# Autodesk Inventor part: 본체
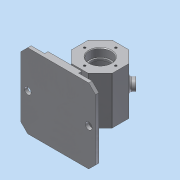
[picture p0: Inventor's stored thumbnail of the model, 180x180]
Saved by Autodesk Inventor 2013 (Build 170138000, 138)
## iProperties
Created: 2018-06
Part Number: 본체
Material: 알루미늄 6061
Document SubType Name: Modeling
Designer: Administrator
Density: 2.71 g/cm^3
Mass: 554.044 g
Surface Area: 601.935 cm^2
Volume: 204.444 cm^3
Author: Administrator
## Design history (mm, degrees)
sketch "스케치1" dims "d0" = 60
  geometry: L1 (12.426, 30)-(30, 12.426); L2 (30, 12.426)-(30, -12.426); L3 (30, -12.426)-(12.426, -30); L4 (12.426, -30)-(-12.426, -30); L5 (-12.426, -30)-(-30, -12.426); L6 (-30, -12.426)-(-30, 12.426); L7 (-30, 12.426)-(-12.426, 30); L8 (-12.426, 30)-(12.426, 30); L9 (55, -62)-(-55, -62); L10 (-55, -62)-(-55, -57); L11 (-55, -57)-(55, -57); L12 (55, -57)-(55, -62); 6 further points
  constraints: 24 end point, 3 coincident, 3 vertical alignment, 2 midpoint, 2 parallel, 1 horizontal, 1 perpendicular, 19 other
  dimensions: "d1" = 5 distance of L9.end L10.end; "d2" = 62 distance from line of point (0, 0) L9; "d3" = 110 distance of L9.start L9.end
extrude "돌출1" new body sketch "스케치1" stored distance "d4" = 70; taper "d5" = 0 deg
extrude "돌출2" join sketch "스케치1" stored distance "d6" = 110; taper "d7" = 0 deg
sketch "스케치2"
  geometry: L1 (0, 0)-(0, 110) reference; L2 (110, 0)-(0, 0) reference; L3 (110, 0)-(110, 110) reference; L4 (0, 110)-(110, 110) reference; L5 (30, 110)-(80, 110); L6 (80, 110)-(80, 0); L7 (80, 0)-(30, 0); L8 (30, 0)-(30, 110); 1 further point
  constraints: 8 end point, 2 parallel, 1 collinear, 1 horizontal, 1 perpendicular, 1 point on line
  dimensions: "d9" = 30 distance between parallel lines of L1 L8; "d10" = 30 distance between parallel lines of L3 L6
extrude "돌출3" join sketch "스케치2" distance "d11" = 5; taper "d12" = 0 deg
hole "구멍1" diameter "d15" = 28; stored, may be unused: countersink angle "d19" = 90 deg, drill point angle "d21" = 0 deg; dims "d13" = 30, "d14" = 30, "d16" = 6, "d17" = 4, "d18" = 2, "d20" = 12
hole "구멍2" diameter "d24" = 32; stored, may be unused: countersink angle "d28" = 90 deg, drill point angle "d30" = 0 deg; dims "d22" = 10, "d23" = 10, "d25" = 6, "d26" = 4, "d27" = 2, "d29" = 12
hole "구멍3" diameter "d33" = 32; stored, may be unused: countersink angle "d37" = 90 deg, drill point angle "d39" = 0 deg; dims "d31" = 10, "d32" = 10, "d34" = 6, "d35" = 4, "d36" = 2, "d38" = 12
sketch "스케치3"
  geometry: L1 (16, 23)-(16, 35) reference; L2 (16, 35)-(30, 35) reference; L3 (30, 35)-(30, -35) reference; L4 (30, -35)-(16, -35) reference; L5 (16, -35)-(16, -23) reference; L6 (16, -23)-(14, -23) reference; L7 (14, -23)-(14, 23) reference; L8 (14, 23)-(16, 23) reference; L9 (-16, 35)-(-16, 23) reference; L10 (-16, 23)-(-14, 23) reference; L11 (-14, 23)-(-14, -23) reference; L12 (-14, -23)-(-16, -23) reference; L13 (-16, -23)-(-16, -35) reference; L14 (-16, -35)-(-30, -35) reference; L15 (-30, -35)-(-30, 35) reference; L16 (-30, 35)-(-16, 35) reference; L17 (-52, 55)-(-52, -55) reference; L18 (-52, -55)-(-62, -55) reference; L19 (-62, -55)-(-62, 55) reference; L20 (-62, 55)-(-52, 55) reference; L21 (0, 20)-(22, 20); L22 (25, 17)-(25, -17); L23 (22, -20)-(0, -20); L24 (0, -20)-(0, 20); A1 r 3 centre (22, 17) between (25, 17) and (22, 20); A2 r 3 centre (22, -17) between (22, -20) and (25, -17); 4 further points
  constraints: 8 end point, 4 point on circle, 4 point on line, 4 tangent, 2 centre point, 2 parallel, 1 coincident, 1 equal radius, 1 horizontal, 1 midpoint, 1 perpendicular
  dimensions: "d40" = 40 distance of L23.end L21.start; "d42" = 20 distance from line of L21 point (0, 0); "d43" = 25 distance of L21.start point (25, 20); "d45" = 3 radius of A1
revolve "회전1" sketch "스케치3" stored, may be unused: angle "d44" = 90 deg
sketch "스케치4"
  geometry: C1 r 16 at (0, 0) reference; 1 further point
  constraints: 1 vertical alignment
  dimensions: "d46" = 23 distance of C1.centre point (0, 23)
hole "구멍4" sketch "스케치4" at (0, 23) diameter "d47" = 3.242; stored, may be unused: countersink angle "d51" = 90 deg, drill point angle "d53" = 118 deg; dims "d48" = 8, "d49" = 4, "d50" = 2, "d52" = 10
sketch "스케치5"
  geometry: L1 (30, 110)-(30, 0) reference; L2 (30, 0)-(80, 0) reference; L3 (50, 36)-(50, 74); L4 (60, 74)-(60, 36); L5 (0, 0)-(0, 110) reference; A1 r 5 centre (55, 74) between (60, 74) and (50, 74); A2 r 5 centre (55, 36) between (50, 36) and (60, 36); 2 further points
  constraints: 4 end point, 4 point on circle, 4 tangent, 2 centre point, 2 midpoint, 1 horizontal alignment, 1 parallel, 1 perpendicular
  dimensions: "d57" = 38 distance of A1.centre A2.centre; "d59" = 5 radius of A2; "d60" = 55 distance from line of L5 A1.centre
extrude "돌출4" join sketch "스케치5" stored distance "d61" = 5; taper "d62" = 0 deg
sketch "스케치6"
  geometry: L1 (-110, 0)-(-110, 110) reference; C1 r 5 at (-100, 55); 2 further points
  constraints: 1 centre point, 1 horizontal alignment, 1 midpoint
  dimensions: "d63" = 10 diameter of C1; "d64" = 10 distance from line of L1 C1.centre
extrude "돌출5" cut sketch "스케치6" distance "d65" = 5; taper "d66" = 0 deg
chamfer "모따기1" distance "d67" = 10; stored, may be unused: second distance "d68" = 2, angle "d69" = 45 deg
sketch "스케치7"
  geometry: L1 (50, -57)-(55, -57) reference; L2 (55, -57)-(55, -62) reference; L3 (55, -62)-(50, -62) reference; L4 (50, -62)-(50, -57) reference; L5 (-55, -57)-(-50, -57) reference; L6 (-50, -57)-(-50, -62) reference; L7 (-50, -62)-(-55, -62) reference; L8 (-55, -62)-(-55, -57) reference; L9 (30, 12.426)-(30, -12.426) reference; L10 (30, -12.426)-(12.426, -30) reference; L11 (12.426, -30)-(5, -30) reference; L12 (5, -30)-(5, -52) reference; L13 (5, -52)-(25, -52) reference; L14 (25, -52)-(25, -57) reference; L15 (25, -57)-(40, -57) reference; L16 (40, -57)-(40, -62) reference; L17 (40, -62)-(-40, -62) reference; L18 (-40, -62)-(-40, -57) reference; L19 (-40, -57)-(-25, -57) reference; L20 (-25, -57)-(-25, -52) reference; L21 (-25, -52)-(-5, -52) reference; L22 (-5, -52)-(-5, -30) reference; L23 (-5, -30)-(-12.426, -30) reference; L24 (-12.426, -30)-(-30, -12.426) reference; L25 (-30, -12.426)-(-30, 12.426) reference; L26 (-30, 12.426)-(-12.426, 30) reference; L27 (-12.426, 30)-(12.426, 30) reference; L28 (12.426, 30)-(30, 12.426) reference; L29 (17.574, 0)-(0, 0); L30 (0, 0)-(26.163, 26.163); C1 r 25 at (0, 0) reference; 1 further point
  constraints: 4 end point, 1 parallel, 1 perpendicular
  dimensions: "d70" = 37 distance of L29.end L30.end
  node "절단 모서리 투영2"
node "작업 평면1"
sketch "스케치8"
  geometry: C1 r 8 at (0, 0); 1 further point
  constraints: 1 centre point, 1 coincident
  dimensions: "d71" = 16 diameter of C1
extrude "돌출6" join sketch "스케치8" stored distance "d72" = 0; taper "d73" = 0 deg
hole "구멍5" diameter "d76" = 8; stored, may be unused: countersink angle "d80" = 90 deg, drill point angle "d82" = 118 deg; dims "d74" = 10, "d75" = 10, "d77" = 8, "d78" = 4, "d79" = 2, "d81" = 30
fillet "모깎기1" dims "d83" = 2
chamfer "모따기2" distance "d84" = 1; stored, may be unused: second distance "d85" = 2, angle "d86" = 45 deg
sketch "스케치9"
  geometry: L1 (24.853, 0)-(0, 0) reference; L2 (-17.574, 0)-(-17.574, 70) reference; 2 further points
  constraints: 1 other
  dimensions: "d87" = 35 distance from line of L1 point (12.426, 35); "d88" = 30 distance from line of L2 point (12.426, 35)
feature "엠보싱1" sketch "스케치9" dims "d89" = 0.5, "d90" = 0
fillet "모깎기2" dims "d91" = 0.3
fillet "모깎기3" dims "d92" = 1
fillet "모깎기4" dims "d93" = 3
node "솔리드1"
pattern_circular "원형 패턴1" dims angle "d55" = 360 deg
mirror "대칭1"
mirror "대칭2"
node "절단 모서리 투영1"
